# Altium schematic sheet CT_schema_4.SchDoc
size 287 x 169 mm
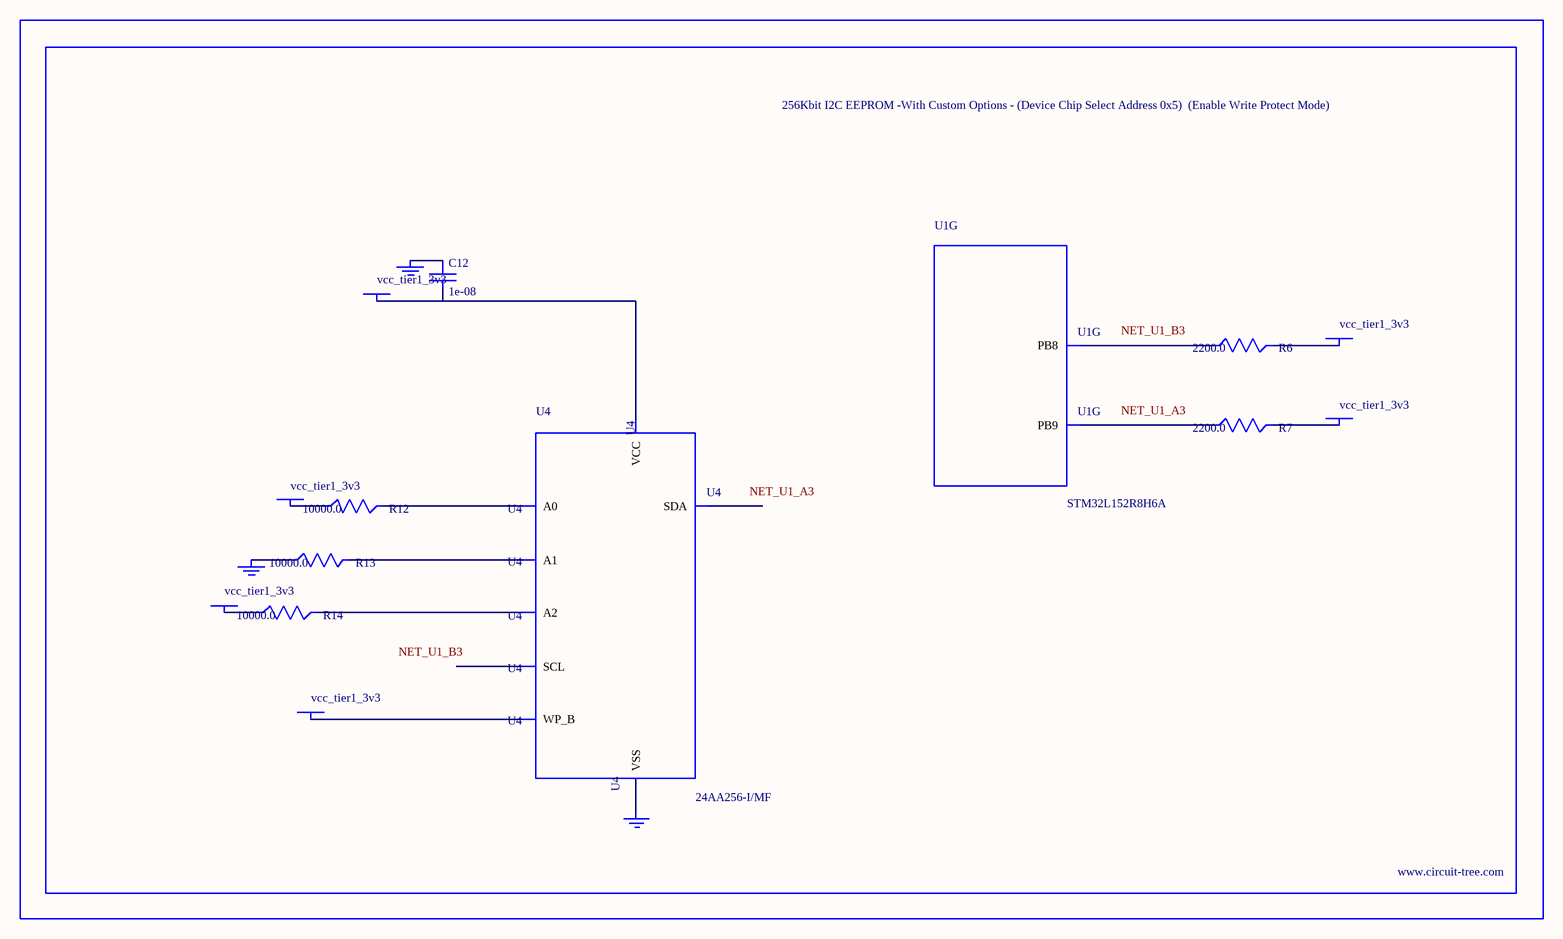
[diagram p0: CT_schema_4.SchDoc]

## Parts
BORDER3  (no value)
C12  1e-08  [C0402]
GND_INSTANCE_3_0  (no value)
GND_INSTANCE_3_1  (no value)
GND_INSTANCE_3_2  (no value)
POWER_INSTANCE_3_0  vcc_tier1_3v3
POWER_INSTANCE_3_1  vcc_tier1_3v3
POWER_INSTANCE_3_2  vcc_tier1_3v3
POWER_INSTANCE_3_3  vcc_tier1_3v3
POWER_INSTANCE_3_4  vcc_tier1_3v3
POWER_INSTANCE_3_5  vcc_tier1_3v3
R6  2200.0  [R0603]
R7  2200.0  [R0603]
R12  10000.0  [R0603]
R13  10000.0  [R0603]
R14  10000.0  [R0603]
U1  STM32L152R8H6A  [TFBGA64]  (part G of 7)
U4  24AA256-I/MF  [DFN8-S]

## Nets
NetC12_1: C12.1 GND_INSTANCE_3_1.0(GND)
NetC12_2: C12.2 POWER_INSTANCE_3_3.0(PWR) U4.8(VCC)
NetGND_INSTANCE_3_0_0: GND_INSTANCE_3_0.0(GND) R13.1
NetGND_INSTANCE_3_2_0: GND_INSTANCE_3_2.0(GND) U4.4(VSS)
NetPOWER_INSTANCE_3_0_0: POWER_INSTANCE_3_0.0(PWR) R12.1
NetPOWER_INSTANCE_3_1_0: POWER_INSTANCE_3_1.0(PWR) R14.1
NetPOWER_INSTANCE_3_2_0: POWER_INSTANCE_3_2.0(PWR) U4.7(WP_B)
NetPOWER_INSTANCE_3_4_0: POWER_INSTANCE_3_4.0(PWR) R6.2
NetPOWER_INSTANCE_3_5_0: POWER_INSTANCE_3_5.0(PWR) R7.2
NetR6_1: R6.1 U1.B3(PB8)
NetR7_1: R7.1 U1.A3(PB9)
NetR12_2: R12.2 U4.1(A0)
NetR13_2: R13.2 U4.2(A1)
NetR14_2: R14.2 U4.3(A2)

Not connected (* = marked no-connect by the designer): U4 5(SDA) 6(SCL)

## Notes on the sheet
- Labels drawn without touching a wire or pin: NET_U1_A3, NET_U1_B3

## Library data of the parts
BORDER3 = BORDER_PAGE3
C12 = C0402C103K3RAC
GND_INSTANCE_3_0-GND_INSTANCE_3_2 = GND
POWER_INSTANCE_3_0-POWER_INSTANCE_3_5 = PWR
R6 R7 = RC0603JR-072K2L
R12-R14 = RC0603JR-0710KL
